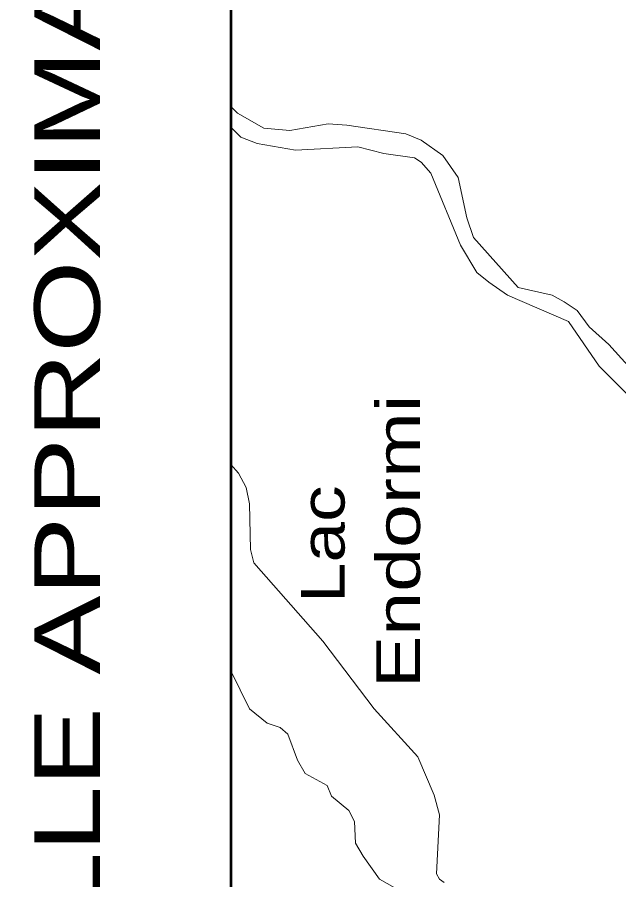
# Model space of a CAD drawing. Extents: x 240591 to 242335, y 5323482 to 5326937.
# Drawn here: x 241431.3 to 241486.4, y 5326602 to 5326681.1 of the extents above; entities that cross this region are included whole.
import ezdxf
from ezdxf.enums import TextEntityAlignment as Align

# ---------------------------------------------------------------- set-up
doc = ezdxf.new("R2010")
doc.units = 0
doc.header["$LTSCALE"] = 1.2
doc.layers.add('63', color=7, linetype='Continuous', lineweight=13)

msp = doc.modelspace()

# ---------------------------------------------------------------- linework, layer by layer
at = {"layer": '63', "lineweight": 53}
msp.add_lwpolyline([(241606.9, 5326533.9), (241606.9, 5326741.9), (241450.9, 5326741.9), (241450.9, 5326533.9)], close=True, dxfattribs=at)
at = {"layer": '63'}
for points in [[(241450.9, 5326672.9), (241451.5, 5326672.3), (241453.9, 5326670.9), (241456.3, 5326670.7), (241459.8, 5326671.3), (241461.5, 5326671.2), (241466.9, 5326670.4), (241468.3, 5326669.8), (241470.3, 5326668.4), (241471.7, 5326666.4), (241472.5, 5326662.7), (241473.1, 5326660.9), (241477.2, 5326656.3), (241480.3, 5326655.6), (241481.4, 5326655), (241482.6, 5326654.2), (241483.7, 5326652.7), (241485.5, 5326651.1), (241488.1, 5326648.2)], [(241450.9, 5326672.9), (241450.9, 5326671), (241451.8, 5326670.1), (241453.3, 5326669.5), (241456.8, 5326668.9), (241462.5, 5326669.2), (241464.9, 5326668.6), (241467.7, 5326668.2), (241468.3, 5326667.8), (241469.2, 5326666.8), (241471.9, 5326660.2), (241473.4, 5326657.7), (241474.5, 5326656.8), (241476.2, 5326655.6), (241481.8, 5326653.2), (241484.6, 5326649.1), (241487.5, 5326646.2)], [(241488.1, 5326648.2), (241485.5, 5326651.1), (241483.7, 5326652.7), (241482.6, 5326654.2), (241481.4, 5326655), (241480.3, 5326655.6), (241477.2, 5326656.3), (241473.1, 5326660.9), (241472.5, 5326662.7), (241471.7, 5326666.4), (241470.3, 5326668.4), (241468.3, 5326669.8), (241466.9, 5326670.4), (241461.5, 5326671.2), (241459.8, 5326671.3), (241456.3, 5326670.7), (241453.9, 5326670.9), (241451.5, 5326672.3), (241450.9, 5326672.9)], [(241450.9, 5326671), (241451.8, 5326670.1), (241453.3, 5326669.5), (241456.8, 5326668.9), (241462.5, 5326669.2), (241464.9, 5326668.6), (241467.7, 5326668.2), (241468.3, 5326667.8), (241469.2, 5326666.8), (241471.9, 5326660.2), (241473.4, 5326657.7), (241474.5, 5326656.8), (241476.2, 5326655.6), (241481.8, 5326653.2), (241484.6, 5326649.1), (241487.5, 5326646.2), (241489.9, 5326645.2), (241490.2, 5326645.1), (241493.6, 5326644.7)], [(241470.4, 5326601.8), (241470, 5326602.1), (241469.7, 5326602.6), (241470, 5326608), (241469.5, 5326609.8), (241468, 5326613.3), (241464, 5326617.7), (241459.3, 5326623.9), (241453, 5326631.1), (241452.7, 5326632.3), (241452.6, 5326636.5), (241452.3, 5326638), (241451.6, 5326639.3), (241450.9, 5326640.1)], [(241470.4, 5326601.8), (241470, 5326602.1), (241469.7, 5326602.6), (241470, 5326608), (241469.5, 5326609.8), (241468, 5326613.3), (241464, 5326617.7), (241459.3, 5326623.9), (241453, 5326631.1), (241452.7, 5326632.3), (241452.6, 5326636.5), (241452.3, 5326638), (241451.6, 5326639.3), (241450.9, 5326640.1), (241450.9, 5326621.2), (241452.6, 5326617.7), (241454.2, 5326616.4), (241455.4, 5326616), (241456.1, 5326615.4), (241457, 5326613), (241457.7, 5326611.8), (241459.7, 5326610.7), (241460.1, 5326609.7), (241461.7, 5326608.4), (241462.2, 5326607.4), (241462.3, 5326605.4), (241463, 5326604.2), (241464.5, 5326602.1), (241465.9, 5326601.3)], [(241465.9, 5326601.3), (241464.5, 5326602.1), (241463, 5326604.2), (241462.3, 5326605.4), (241462.2, 5326607.4), (241461.7, 5326608.4), (241460.1, 5326609.7), (241459.7, 5326610.7), (241457.7, 5326611.8), (241457, 5326613), (241456.1, 5326615.4), (241455.4, 5326616), (241454.2, 5326616.4), (241452.6, 5326617.7), (241450.9, 5326621.2)]]:
    msp.add_lwpolyline(points, dxfattribs=at)

# ---------------------------------------------------------------- texts
at = {"layer": '63', "width": 1.35}
msp.add_text('ÉCHELLE APPROXIMATIVE 1 : 75 000', height=6, rotation=90, dxfattribs=at).set_placement((241438.9, 5326664.5), align=Align.CENTER)
at = {"layer": '63'}
for s, width, p in [('Endormi', 1.35, (241468.2, 5326619.6)), ('Lac', 1.25, (241461.3, 5326627.4))]:
    msp.add_text(s, height=4, rotation=90, dxfattribs=dict(at, width=width)).set_placement(p)

doc.saveas('drawing.dxf')
